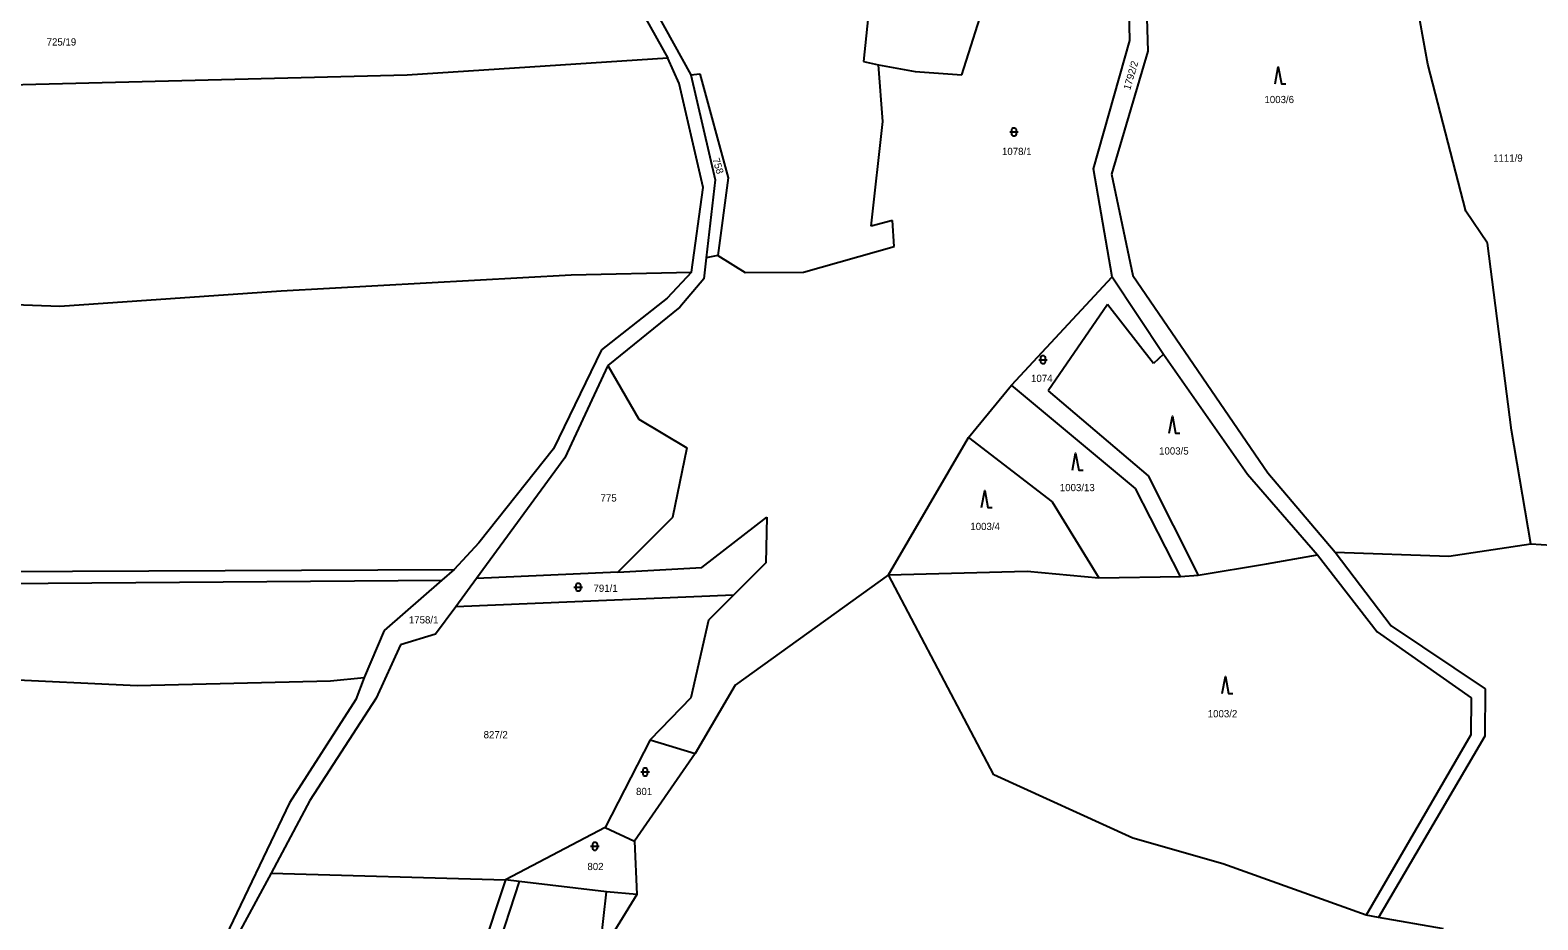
# Model space of a CAD drawing. Extents: x -799786 to -795190, y -1021716 to -1017834.
# Drawn here: x -798982.6 to -798627.9, y -1019794.2 to -1019585 of the extents above; entities that cross this region are included whole.
import ezdxf

# ---------------------------------------------------------------- set-up
doc = ezdxf.new("R2010")
doc.units = 0
for name, color, linetype in [('Default', 7, 'Continuous'), ('KN_HRANICE', 7, 'Continuous'), ('KN_KULTURY', 7, 'Continuous'), ('KN_PARCELY', 7, 'Continuous')]:
    doc.layers.add(name, color=color, linetype=linetype)

# ---------------------------------------------------------------- blocks, each defined once
blk = doc.blocks.new('308')
at = {"layer": 'Default'}
blk.add_lwpolyline([(-0.75, 0), (0, 4), (0.75, 0), (1.75, 0)], dxfattribs=at)
blk = doc.blocks.new('316')
at = {"layer": 'Default'}
for points in [[(-1, 1), (0.27, 1), (1, 1)], [(-0.5, 1.5), (-0.4, 1.79), (-0.15, 1.97), (0.16, 1.97), (0.41, 1.79), (0.51, 1.5), (0.51, 0.5), (0.41, 0.21), (0.16, 0.03), (-0.15, 0.03), (-0.4, 0.21), (-0.5, 0.5), (-0.5, 1.5)]]:
    blk.add_lwpolyline(points, dxfattribs=at)

msp = doc.modelspace()

# ---------------------------------------------------------------- linework, layer by layer
at = {"layer": 'KN_HRANICE'}
for p, q in [((-798721.17, -1019529.97), (-798719.63, -1019589.9)), ((-798763.39, -1019595.46), (-798753.06, -1019563.2)), ((-798723.85, -1019587.37), (-798724.33, -1019563.53)), ((-798841.6, -1019569.19), (-798827.09, -1019595.48)), ((-798653.74, -1019592.96), (-798658.38, -1019567.59)), ((-798843.91, -1019571.19), (-798832.55, -1019591.58)), ((-798784.99, -1019577.96), (-798786.52, -1019592.32)), ((-798732.38, -1019617.59), (-798723.85, -1019587.37)), ((-798832.55, -1019591.58), (-798893.88, -1019595.58)), ((-798829.83, -1019597.48), (-798832.55, -1019591.58)), ((-798719.63, -1019589.9), (-798728.17, -1019618.85)), ((-798893.88, -1019595.58), (-799004.28, -1019598.31)), ((-798827.09, -1019595.48), (-798824.98, -1019595.27)), ((-798827.09, -1019595.48), (-798821.4, -1019620.15)), ((-798824.98, -1019595.27), (-798818.35, -1019619.72)), ((-798786.52, -1019592.32), (-798782.94, -1019593.16)), ((-798781.99, -1019606.44), (-798782.94, -1019593.16)), ((-798782.94, -1019593.16), (-798774.35, -1019594.72)), ((-798774.35, -1019594.72), (-798763.39, -1019595.46)), ((-798644.79, -1019627.58), (-798653.74, -1019592.96)), ((-798824.25, -1019621.94), (-798829.83, -1019597.48)), ((-798784.73, -1019631.11), (-798781.99, -1019606.44)), ((-798821.4, -1019620.15), (-798823.51, -1019638.49)), ((-798818.35, -1019619.72), (-798820.77, -1019637.96)), ((-798727.97, -1019642.95), (-798732.38, -1019617.59)), ((-798728.17, -1019618.85), (-798723.13, -1019642.64)), ((-798826.98, -1019641.9), (-798824.25, -1019621.94)), ((-798639.73, -1019635.07), (-798644.79, -1019627.58)), ((-798779.67, -1019629.74), (-798784.73, -1019631.11)), ((-798779.25, -1019635.85), (-798779.67, -1019629.74)), ((-798820.77, -1019637.96), (-798823.51, -1019638.49)), ((-798820.77, -1019637.96), (-798814.34, -1019641.97)), ((-798800.64, -1019641.86), (-798779.25, -1019635.85)), ((-798634.06, -1019679.05), (-798639.73, -1019635.07)), ((-798823.51, -1019638.49), (-798824.03, -1019643.48)), ((-798814.34, -1019641.97), (-798800.64, -1019641.86)), ((-798923.52, -1019646.27), (-798855.24, -1019642.54)), ((-798855.24, -1019642.54), (-798826.98, -1019641.9)), ((-798826.98, -1019641.9), (-798832.67, -1019648.01)), ((-798824.03, -1019643.48), (-798829.72, -1019650.12)), ((-798751.67, -1019668.43), (-798727.97, -1019642.95)), ((-798727.97, -1019642.95), (-798715.96, -1019661.19)), ((-798723.13, -1019642.64), (-798691.41, -1019689.12)), ((-799030.13, -1019647.8), (-798975.55, -1019649.9)), ((-798975.55, -1019649.9), (-798923.52, -1019646.27)), ((-798832.67, -1019648.01), (-798848.16, -1019660.14)), ((-798829.72, -1019650.12), (-798846.65, -1019663.85)), ((-798729.13, -1019649.49), (-798743.03, -1019669.8)), ((-798718.28, -1019663.4), (-798729.13, -1019649.49)), ((-798848.16, -1019660.14), (-798859.44, -1019683.43)), ((-798715.96, -1019661.19), (-798718.28, -1019663.4)), ((-798715.96, -1019661.19), (-798696.15, -1019689.44)), ((-798846.65, -1019663.85), (-798856.76, -1019685.57)), ((-798846.65, -1019663.85), (-798839.38, -1019676.5)), ((-798761.79, -1019680.76), (-798751.67, -1019668.43)), ((-798722.49, -1019692.78), (-798751.67, -1019668.43)), ((-798743.03, -1019669.8), (-798719.54, -1019689.83)), ((-798839.38, -1019676.5), (-798828.03, -1019683.22)), ((-798780.64, -1019713.08), (-798761.79, -1019680.76)), ((-798761.79, -1019680.76), (-798742.09, -1019695.94)), ((-798629.51, -1019705.82), (-798634.06, -1019679.05)), ((-798859.44, -1019683.43), (-798877.02, -1019705.56)), ((-798828.03, -1019683.22), (-798831.47, -1019699.59)), ((-798856.76, -1019685.57), (-798877.54, -1019713.98)), ((-798719.54, -1019689.83), (-798707.74, -1019713.13)), ((-798696.15, -1019689.44), (-798679.66, -1019708.35)), ((-798691.41, -1019689.12), (-798675.55, -1019707.72)), ((-798711.95, -1019713.44), (-798722.49, -1019692.78)), ((-798742.09, -1019695.94), (-798731.11, -1019713.81)), ((-798831.47, -1019699.59), (-798844.33, -1019712.45)), ((-798824.52, -1019711.39), (-798809.24, -1019699.48)), ((-798809.24, -1019699.48), (-798809.45, -1019710.24)), ((-798877.02, -1019705.56), (-798882.81, -1019711.83)), ((-798691.7, -1019710.51), (-798679.66, -1019708.35)), ((-798679.66, -1019708.35), (-798665.65, -1019726.48)), ((-798675.55, -1019707.72), (-798648.79, -1019708.66)), ((-798675.55, -1019707.72), (-798662.38, -1019725.11)), ((-798648.79, -1019708.66), (-798629.51, -1019705.82)), ((-798629.51, -1019705.82), (-798602.59, -1019707.48)), ((-799012.43, -1019712.36), (-798882.81, -1019711.83)), ((-798882.81, -1019711.83), (-798885.71, -1019714.35)), ((-798844.33, -1019712.45), (-798877.54, -1019713.98)), ((-798844.33, -1019712.45), (-798824.52, -1019711.39)), ((-798809.45, -1019710.24), (-798817.09, -1019717.88)), ((-798780.64, -1019713.08), (-798747.97, -1019712.23)), ((-798747.97, -1019712.23), (-798731.11, -1019713.81)), ((-798707.74, -1019713.13), (-798691.7, -1019710.51)), ((-798988.55, -1019715.09), (-798885.71, -1019714.35)), ((-798885.71, -1019714.35), (-798899.3, -1019726.15)), ((-798877.54, -1019713.98), (-798882.44, -1019720.57)), ((-798780.64, -1019713.08), (-798816.66, -1019739.02)), ((-798755.87, -1019760.09), (-798780.64, -1019713.08)), ((-798731.11, -1019713.81), (-798711.95, -1019713.44)), ((-798711.95, -1019713.44), (-798707.74, -1019713.13)), ((-798817.09, -1019717.88), (-798882.44, -1019720.57)), ((-798817.09, -1019717.88), (-798822.94, -1019723.73)), ((-798882.44, -1019720.57), (-798887.21, -1019727.01)), ((-798899.3, -1019726.15), (-798903.97, -1019737.24)), ((-798822.94, -1019723.73), (-798827.15, -1019742.01)), ((-798665.65, -1019726.48), (-798643.52, -1019741.98)), ((-798662.38, -1019725.11), (-798640.25, -1019739.87)), ((-798895.43, -1019729.54), (-798901.12, -1019742.09)), ((-798887.21, -1019727.01), (-798895.43, -1019729.54)), ((-799016.36, -1019736.35), (-798957.39, -1019739.14)), ((-798911.86, -1019738.04), (-798903.97, -1019737.24)), ((-798903.97, -1019737.24), (-798905.97, -1019742.4)), ((-798957.39, -1019739.14), (-798911.86, -1019738.04)), ((-798816.66, -1019739.02), (-798826.13, -1019755.13)), ((-798640.25, -1019739.87), (-798640.36, -1019751.04)), ((-798905.97, -1019742.4), (-798921.54, -1019766.7)), ((-798901.12, -1019742.09), (-798916.79, -1019766.17)), ((-798827.15, -1019742.01), (-798836.67, -1019751.86)), ((-798643.52, -1019741.98), (-798643.63, -1019750.72)), ((-798643.63, -1019750.72), (-798668.27, -1019793.15)), ((-798640.36, -1019751.04), (-798665.32, -1019793.68)), ((-798836.67, -1019751.86), (-798847.3, -1019772.48)), ((-798826.13, -1019755.13), (-798840.35, -1019775.69)), ((-798836.67, -1019751.86), (-798826.13, -1019755.13)), ((-798723.16, -1019775.02), (-798755.87, -1019760.09)), ((-798921.54, -1019766.7), (-798937.42, -1019799.96)), ((-798916.79, -1019766.17), (-798925.86, -1019783.25)), ((-798847.3, -1019772.48), (-798870.69, -1019784.81)), ((-798847.3, -1019772.48), (-798840.35, -1019775.69)), ((-798840.35, -1019775.69), (-798839.82, -1019788.29)), ((-798701.98, -1019781.03), (-798723.16, -1019775.02)), ((-798925.86, -1019783.25), (-798935.63, -1019801.33)), ((-798925.86, -1019783.25), (-798870.69, -1019784.81)), ((-798668.27, -1019793.15), (-798701.98, -1019781.03)), ((-798870.69, -1019784.81), (-798882.07, -1019818.86)), ((-798867.48, -1019785.23), (-798878.91, -1019819.91)), ((-798867.48, -1019785.23), (-798870.69, -1019784.81)), ((-798846.93, -1019787.66), (-798867.48, -1019785.23)), ((-798839.82, -1019788.29), (-798862.47, -1019825.11)), ((-798848.35, -1019800.2), (-798846.93, -1019787.66)), ((-798839.82, -1019788.29), (-798846.93, -1019787.66)), ((-798665.32, -1019793.68), (-798668.27, -1019793.15)), ((-798650.08, -1019796.37), (-798665.32, -1019793.68))]:
    msp.add_line(p, q, dxfattribs=at)

# ---------------------------------------------------------------- block references
at = {"layer": 'KN_KULTURY'}
for name, p in [('308', (-798688.91, -1019597.58)), ('316', (-798751.11, -1019609.91)), ('316', (-798744.27, -1019663.48)), ('308', (-798713.83, -1019679.79)), ('308', (-798736.61, -1019688.46)), ('308', (-798757.97, -1019697.22)), ('316', (-798853.61, -1019716.98)), ('308', (-798701.37, -1019740.99)), ('316', (-798837.87, -1019760.45)), ('316', (-798849.7, -1019777.91))]:
    msp.add_blockref(name, p, dxfattribs=at)

# ---------------------------------------------------------------- texts
at = {"layer": 'KN_PARCELY'}
for s, p in [('725/19', (-798978.67, -1019588.59)), ('1003/6', (-798692.17, -1019602.13)), ('1078/1', (-798753.92, -1019614.34)), ('1111/9', (-798638.38, -1019615.9)), ('1074', (-798747.08, -1019667.72)), ('1003/5', (-798716.96, -1019684.79)), ('775', (-798848.36, -1019695.84)), ('1003/13', (-798740.31, -1019693.4)), ('1003/4', (-798761.36, -1019702.54)), ('791/1', (-798850.02, -1019717.08)), ('1758/1', (-798893.45, -1019724.51)), ('1003/2', (-798705.51, -1019746.59)), ('827/2', (-798875.87, -1019751.53)), ('801', (-798840.01, -1019764.88)), ('802', (-798851.45, -1019782.53))]:
    msp.add_text(s, height=1.7, dxfattribs=at).set_placement(p)
for s, rotation, p in [('1792/2', 73.74, (-798723.77, -1019599.18)), ('758', 286.823, (-798822.07, -1019615.32))]:
    msp.add_text(s, height=1.7, rotation=rotation, dxfattribs=at).set_placement(p)

doc.saveas('drawing.dxf')
